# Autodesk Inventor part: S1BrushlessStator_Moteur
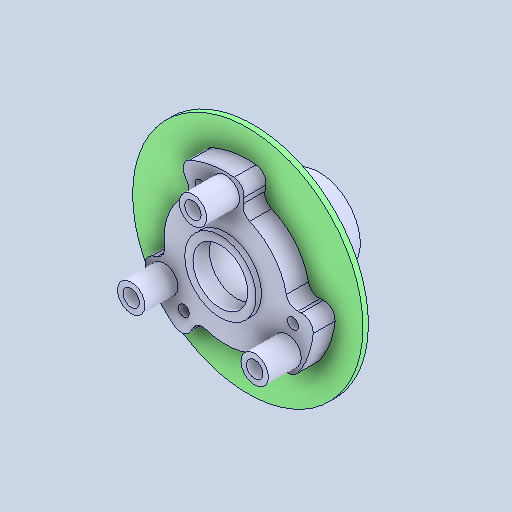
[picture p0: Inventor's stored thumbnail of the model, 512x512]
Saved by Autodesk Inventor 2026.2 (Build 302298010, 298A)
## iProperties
Created: 1601-01
Part Number: S1BrushlessStator_Moteur
Material: Générique
Document SubType Name: Modeling
Designer: mel
Density: 1 g/cm^3
Appearance: Par défaut
Author: mel
Sending System: SOLIDWORKS 2023
Part Number: Stator_Moteur
Last Saved Date: 2025-04-02
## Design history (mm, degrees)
feature "Enlèv. mat.-Extru.2"
node "Solide1"
